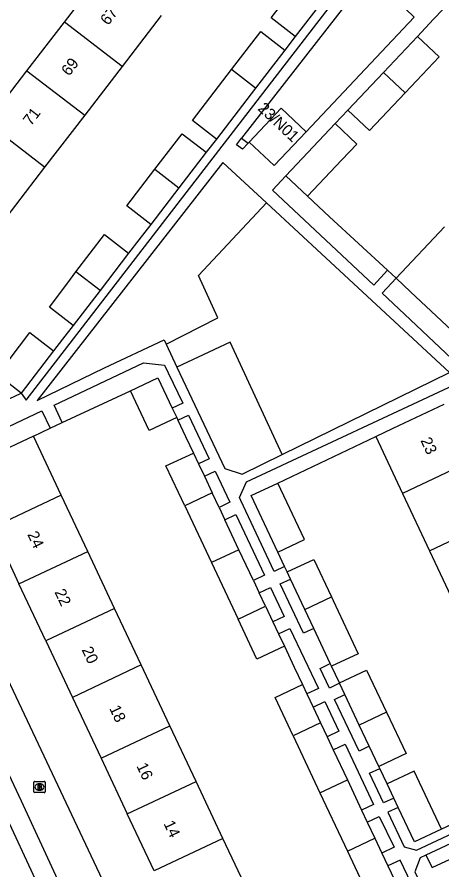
# Model space of a CAD drawing. Extents: x 159040 to 160094, y 381214 to 382518.
# Drawn here: x 159164.4 to 159201.9, y 381381.3 to 381456.6 of the extents above; entities that cross this region are included whole.
import ezdxf

# ---------------------------------------------------------------- set-up
doc = ezdxf.new("R2010")
doc.units = 0
for name, color, linetype in [('IMGEO_Brandkraan', 7, 'Continuous'), ('IMGEO_Groenvoorziening', 7, 'Continuous'), ('IMGEO_Pand', 7, 'Continuous'), ('IMGEO_Pand_nummerreeks', 7, 'Continuous'), ('IMGEO_Rijbaan_lokaal_open', 7, 'Continuous'), ('IMGEO_Voetpad_open', 7, 'Continuous')]:
    doc.layers.add(name, color=color, linetype=linetype)

msp = doc.modelspace()

# ---------------------------------------------------------------- linework, layer by layer
at = {"layer": 'IMGEO_Brandkraan'}
for p, q in [((159165.843, 381388.151), (159165.843, 381389.003)), ((159165.918, 381389.077), (159166.77, 381389.077)), ((159166.331, 381388.857), (159166.356, 381388.857)), ((159166.844, 381389.003), (159166.844, 381388.151)), ((159166.77, 381388.077), (159165.918, 381388.077)), ((159166.354, 381388.297), (159166.329, 381388.297))]:
    msp.add_line(p, q, dxfattribs=at)
for points in [[(159165.843, 381388.151), (159165.843, 381389.003)], [(159165.918, 381389.077), (159166.77, 381389.077)], [(159166.191, 381388.777), (159166.191, 381388.377), (159166.404, 381388.377)], [(159166.422, 381388.777), (159166.191, 381388.777)], [(159166.37, 381388.696), (159166.316, 381388.696), (159166.316, 381388.62)], [(159166.844, 381389.003), (159166.844, 381388.151)], [(159166.77, 381388.077), (159165.918, 381388.077)], [(159166.316, 381388.62), (159166.369, 381388.62)], [(159166.378, 381388.544), (159166.316, 381388.544), (159166.316, 381388.463)], [(159166.316, 381388.463), (159166.378, 381388.463)]]:
    msp.add_lwpolyline(points, dxfattribs=at)
for centre, radius, start, end in [((159165.92, 381389.001), 0.0765, 91.55205, 178.44795), ((159165.92, 381389.001), 0.0765, 91.55205, 178.44795), ((159166.371, 381388.658), 0.0379, 267.82845, 90.93552), ((159166.426, 381388.632), 0.145, 59.4692, 91.53667), ((159166.451, 381388.679), 0.0922, 285.51372, 58.15012), ((159166.768, 381389.001), 0.0765, 1.55205, 88.44795), ((159166.768, 381389.001), 0.0765, 1.55205, 88.44795), ((159165.92, 381388.153), 0.0765, 181.55205, 268.44795), ((159165.92, 381388.153), 0.0765, 181.55205, 268.44795), ((159166.379, 381388.503), 0.0404, 269.87594, 90.50774), ((159166.41, 381388.628), 0.251, 268.66757, 293.53466), ((159166.456, 381388.487), 0.105, 301.31148, 78.98903), ((159166.768, 381388.153), 0.0765, 271.55205, 358.44795), ((159166.768, 381388.153), 0.0765, 271.55205, 358.44795)]:
    msp.add_arc(centre, radius, start, end, dxfattribs=at)
for centre, major_axis, ratio, start_param, end_param in [((159166.33, 381388.577), (-0.387, 0.002), 0.722429, 4.712389, 7.853982), ((159166.355, 381388.577), (-0.39, 0.002), 0.717154, 1.570796, 4.712389)]:
    msp.add_ellipse(centre, major_axis=major_axis, ratio=ratio, start_param=start_param, end_param=end_param, dxfattribs=at)
at = {"layer": 'IMGEO_Groenvoorziening'}
for points in [[(159188.951, 381454.87), (159188.021, 381453.661)], [(159181.982, 381445.811), (159181.077, 381444.635)], [(159197.1, 381434.226), (159191.975, 381438.93), (159190.037, 381440.758)], [(159177.541, 381427.677), (159182.111, 381430.01), (159180.393, 381433.751), (159186.402, 381440.174)], [(159176.18, 381438.27), (159175.127, 381436.901), (159174.226, 381435.729)], [(159169.317, 381429.348), (159168.391, 381428.145), (159167.593, 381427.107)], [(159187.798, 381417.935), (159183.191, 381427.88), (159178.496, 381425.656)], [(159168.362, 381420.766), (159174.389, 381423.58)], [(159178.583, 381420.967), (159179.258, 381419.536), (159179.948, 381418.072)], [(159165.805, 381419.572), (159167.281, 381420.261)], [(159187.402, 381415.418), (159196.055, 381419.537)], [(159188.009, 381408.05), (159187.41, 381409.321)], [(159187.987, 381401.016), (159188.86, 381399.164), (159189.585, 381397.625)], [(159192.852, 381397.776), (159192.158, 381399.248)], [(159197.057, 381388.853), (159196.416, 381390.214)], [(159200.494, 381382.57), (159201.05, 381381.464), (159217.322, 381389.003)], [(159210.505, 381388.881), (159201.876, 381384.861)]]:
    msp.add_lwpolyline(points, dxfattribs=at)
at = {"layer": 'IMGEO_Pand'}
for points in [[(159188.951, 381454.87), (159186.825, 381456.505), (159190.35, 381461.088)], [(159168.552, 381456.144), (159172.008, 381460.637)], [(159192.476, 381459.453), (159188.951, 381454.87)], [(159177.108, 381456.713), (159173.652, 381452.22)], [(159165.242, 381451.841), (159168.552, 381456.144)], [(159173.652, 381452.22), (159168.552, 381456.144)], [(159183.312, 381451.939), (159185.895, 381455.297), (159188.021, 381453.661)], [(159196.738, 381451.698), (159199.738, 381454.878)], [(159198.653, 381449.893), (159201.652, 381453.073), (159199.738, 381454.878)], [(159188.021, 381453.661), (159185.438, 381450.304)], [(159173.652, 381452.22), (159170.342, 381447.917)], [(159181.982, 381445.811), (159179.856, 381447.447), (159183.312, 381451.939)], [(159185.438, 381450.304), (159183.312, 381451.939)], [(159161.698, 381447.234), (159165.242, 381451.841)], [(159165.242, 381451.841), (159170.342, 381447.917)], [(159193.586, 381448.355), (159196.738, 381451.698)], [(159196.738, 381451.698), (159198.653, 381449.893)], [(159185.438, 381450.304), (159181.982, 381445.811)], [(159198.653, 381449.893), (159195.501, 381446.549), (159193.586, 381448.355)], [(159184.883, 381445.545), (159187.701, 381448.534), (159189.902, 381446.458)], [(159170.342, 381447.917), (159166.798, 381443.31)], [(159166.798, 381443.31), (159161.698, 381447.234)], [(159188.123, 381442.563), (159192.467, 381447.169)], [(159190.037, 381440.758), (159193.078, 381443.981), (159194.382, 381445.363), (159192.467, 381447.169)], [(159176.546, 381443.144), (159178.951, 381446.271), (159181.077, 381444.635)], [(159189.902, 381446.458), (159187.083, 381443.469), (159184.883, 381445.545)], [(159181.077, 381444.635), (159178.671, 381441.508)], [(159166.798, 381443.31), (159163.366, 381438.849)], [(159176.18, 381438.27), (159174.055, 381439.906), (159176.546, 381443.144)], [(159176.546, 381443.144), (159178.671, 381441.508)], [(159188.123, 381442.563), (159190.037, 381440.758)], [(159178.671, 381441.508), (159176.18, 381438.27)], [(159202.137, 381438.049), (159197.867, 381433.522)], [(159169.569, 381434.075), (159172.101, 381437.365), (159174.226, 381435.729)], [(159174.226, 381435.729), (159171.695, 381432.439)], [(159169.317, 381429.348), (159167.226, 381430.956), (159167.879, 381431.805), (159169.077, 381433.435), (159169.569, 381434.075)], [(159171.695, 381432.439), (159169.569, 381434.075)], [(159202.771, 381428.897), (159199.134, 381432.328), (159197.867, 381433.522)], [(159171.695, 381432.439), (159169.317, 381429.348)], [(159164.713, 381423.363), (159162.622, 381424.971), (159165.502, 381428.715), (159167.593, 381427.107)], [(159167.593, 381427.107), (159164.713, 381423.363)], [(159174.389, 381423.58), (159176.813, 381424.723), (159178.082, 381422.031)], [(159178.471, 381421.205), (159176.047, 381420.063), (159174.389, 381423.58)], [(159178.082, 381422.031), (159178.471, 381421.205)], [(159196.055, 381419.537), (159197.587, 381420.259), (159202.109, 381422.391)], [(159165.805, 381419.572), (159164.247, 381418.838), (159159.724, 381416.706)], [(159168.264, 381414.355), (159165.805, 381419.572)], [(159196.055, 381419.537), (159198.423, 381414.513)], [(159179.176, 381413.425), (159177.523, 381416.93), (159179.948, 381418.072)], [(159179.948, 381418.072), (159180.398, 381417.118)], [(159204.477, 381417.367), (159198.423, 381414.513)], [(159180.398, 381417.118), (159180.914, 381416.022)], [(159180.914, 381416.022), (159181.6, 381414.567)], [(159187.41, 381409.321), (159185.057, 381414.313), (159187.402, 381415.418)], [(159187.41, 381409.321), (159189.755, 381410.427), (159187.402, 381415.418)], [(159168.264, 381414.355), (159162.183, 381411.489)], [(159170.606, 381409.386), (159168.264, 381414.355)], [(159181.6, 381414.567), (159179.176, 381413.425)], [(159182.21, 381413.274), (159181.6, 381414.567)], [(159198.423, 381414.513), (159200.81, 381409.45)], [(159179.176, 381413.425), (159181.546, 381408.395)], [(159182.21, 381413.274), (159182.727, 381412.176)], [(159183.971, 381409.537), (159182.727, 381412.176)], [(159200.81, 381409.45), (159206.864, 381412.303)], [(159162.183, 381411.489), (159164.525, 381406.52)], [(159164.525, 381406.52), (159170.606, 381409.386)], [(159172.977, 381404.356), (159170.606, 381409.386)], [(159183.971, 381409.537), (159181.546, 381408.395)], [(159185.258, 381406.805), (159183.971, 381409.537)], [(159200.81, 381409.45), (159203.172, 381404.439)], [(159181.546, 381408.395), (159183.903, 381403.396)], [(159188.231, 381407.58), (159190.575, 381408.686), (159192.141, 381405.364)], [(159188.531, 381406.942), (159188.231, 381407.58)], [(159185.258, 381406.805), (159185.77, 381405.72)], [(159189.796, 381404.259), (159188.531, 381406.942)], [(159166.896, 381401.49), (159164.525, 381406.52)], [(159186.327, 381404.538), (159185.77, 381405.72)], [(159189.796, 381404.259), (159192.141, 381405.364)], [(159192.141, 381405.364), (159192.294, 381405.039), (159194.5, 381400.352), (159192.158, 381399.248)], [(159183.903, 381403.396), (159186.327, 381404.538)], [(159186.327, 381404.538), (159186.977, 381403.158)], [(159172.977, 381404.356), (159166.896, 381401.49)], [(159175.333, 381399.357), (159172.977, 381404.356)], [(159190.585, 381402.585), (159189.796, 381404.259)], [(159187.987, 381401.016), (159185.563, 381399.874), (159183.903, 381403.396)], [(159186.977, 381403.158), (159187.475, 381402.102)], [(159192.047, 381399.483), (159190.585, 381402.585)], [(159166.896, 381401.49), (159169.252, 381396.491)], [(159187.475, 381402.102), (159187.987, 381401.016)], [(159175.333, 381399.357), (159169.252, 381396.491)], [(159177.866, 381393.983), (159175.333, 381399.357)], [(159192.158, 381399.248), (159192.047, 381399.483)], [(159192.852, 381397.776), (159195.255, 381398.909), (159197.01, 381395.185)], [(159192.871, 381397.736), (159192.852, 381397.776)], [(159193.339, 381396.744), (159192.871, 381397.736)], [(159188.751, 381393.11), (159187.161, 381396.483), (159189.585, 381397.625)], [(159189.585, 381397.625), (159189.972, 381396.804)], [(159169.252, 381396.491), (159171.785, 381391.117)], [(159189.972, 381396.804), (159190.524, 381395.633)], [(159194.607, 381394.053), (159193.339, 381396.744)], [(159190.524, 381395.633), (159191.175, 381394.252)], [(159197.01, 381395.185), (159194.607, 381394.053)], [(159197.01, 381395.185), (159198.735, 381391.527), (159196.331, 381390.394)], [(159171.785, 381391.117), (159177.866, 381393.983)], [(159180.181, 381389.071), (159177.866, 381393.983)], [(159191.175, 381394.252), (159188.751, 381393.11)], [(159191.175, 381394.252), (159191.763, 381393.005)], [(159195.492, 381392.174), (159194.607, 381394.053)], [(159188.751, 381393.11), (159191.127, 381388.068)], [(159191.763, 381393.005), (159192.307, 381391.851)], [(159192.307, 381391.851), (159193.551, 381389.21)], [(159196.331, 381390.394), (159195.492, 381392.174)], [(159171.785, 381391.117), (159174.1, 381386.205)], [(159201.876, 381384.861), (159199.461, 381389.986), (159197.057, 381388.853)], [(159174.1, 381386.205), (159180.181, 381389.071)], [(159182.558, 381384.029), (159180.181, 381389.071)], [(159191.127, 381388.068), (159193.551, 381389.21)], [(159193.551, 381389.21), (159194.812, 381386.536)], [(159197.647, 381387.601), (159197.057, 381388.853)], [(159191.127, 381388.068), (159193.552, 381382.924)], [(159198.037, 381386.775), (159197.647, 381387.601)], [(159194.812, 381386.536), (159195.31, 381385.478)], [(159201.876, 381384.861), (159199.473, 381383.728), (159198.037, 381386.775)], [(159176.477, 381381.163), (159174.1, 381386.205)], [(159195.31, 381385.478), (159195.976, 381384.066)], [(159182.558, 381384.029), (159176.477, 381381.163)], [(159184.982, 381378.885), (159182.558, 381384.029)], [(159193.552, 381382.924), (159195.976, 381384.066)], [(159195.976, 381384.066), (159196.602, 381382.737)], [(159193.552, 381382.924), (159196.403, 381376.874)], [(159196.602, 381382.737), (159197.136, 381381.605)], [(159197.136, 381381.605), (159198.827, 381378.016)]]:
    msp.add_lwpolyline(points, dxfattribs=at)
at = {"layer": 'IMGEO_Rijbaan_lokaal_open'}
msp.add_lwpolyline([(159152.42, 381409.329), (159163.115, 381386.6), (159166.148, 381380.052), (159173.158, 381365.109), (159175.314, 381360.345), (159181.799, 381346.618), (159183.007, 381344.058)], dxfattribs=at)
at = {"layer": 'IMGEO_Voetpad_open'}
for points in [[(159164.713, 381423.363), (159165.178, 381422.754), (159206.798, 381476.685), (159206.128, 381477.2)], [(159189.902, 381446.458), (159197.026, 381454.012), (159199.461, 381456.58), (159195.523, 381460.39), (159184.209, 381445.885)], [(159199.738, 381454.878), (159201.159, 381456.385), (159201.975, 381457.25)], [(159192.467, 381447.169), (159193.586, 381448.355)], [(159184.794, 381445.451), (159184.28, 381444.905), (159183.76, 381445.31), (159184.209, 381445.885)], [(159184.209, 381445.885), (159184.794, 381445.451)], [(159184.794, 381445.451), (159184.883, 381445.545)], [(159186.402, 381440.174), (159182.544, 381443.75), (159166.145, 381422.725), (159172.089, 381425.587), (159177.353, 381428.075), (159177.541, 381427.677)], [(159197.1, 381434.226), (159195.879, 381432.896), (159186.938, 381441.307), (159188.123, 381442.563)], [(159187.798, 381417.935), (159202.578, 381425.178), (159186.402, 381440.174)], [(159197.867, 381433.522), (159197.1, 381434.226)], [(159204.41, 381426.076), (159203.808, 381425.437), (159198.609, 381430.327), (159196.621, 381432.198), (159197.867, 381433.522)], [(159177.541, 381427.677), (159178.496, 381425.656)], [(159168.362, 381420.766), (159167.645, 381422.301), (159175.543, 381426.031), (159177.405, 381425.843), (159177.731, 381425.156), (159179.009, 381422.472), (159178.082, 381422.031)], [(159178.496, 381425.656), (159182.727, 381416.701), (159184.263, 381416.202), (159187.798, 381417.935)], [(159188.009, 381408.05), (159187.092, 381407.618), (159184.136, 381413.879), (159184.009, 381414.149), (159184.651, 381415.527), (159203.819, 381424.481)], [(159153.986, 381418.297), (159164.713, 381423.363)], [(159154.931, 381416.296), (159166.567, 381421.792), (159167.281, 381420.261)], [(159178.471, 381421.205), (159178.583, 381420.967)], [(159178.583, 381420.967), (159179.514, 381421.411), (159181.344, 381417.568), (159180.398, 381417.118)], [(159167.281, 381420.261), (159168.362, 381420.766)], [(159180.914, 381416.022), (159181.864, 381416.474), (159183.17, 381413.731), (159182.21, 381413.274)], [(159186.898, 381348.612), (159155.647, 381414.78)], [(159152.189, 381413.877), (159154.272, 381409.573), (159164.73, 381387.348), (159167.763, 381380.799), (159174.777, 381365.849), (159176.928, 381361.094), (159183.083, 381348.082), (159184.313, 381345.459)], [(159182.727, 381412.176), (159183.692, 381412.635), (159186.243, 381407.274), (159185.258, 381406.805)], [(159188.231, 381407.58), (159188.009, 381408.05)], [(159190.585, 381402.585), (159189.672, 381402.155), (159187.615, 381406.51), (159188.531, 381406.942)], [(159185.77, 381405.72), (159186.759, 381406.191), (159187.977, 381403.633), (159186.977, 381403.158)], [(159187.475, 381402.102), (159188.478, 381402.58), (159190.995, 381397.292), (159189.972, 381396.804)], [(159192.871, 381397.736), (159191.961, 381397.307), (159191.136, 381399.054), (159192.047, 381399.483)], [(159195.492, 381392.174), (159194.586, 381391.748), (159192.429, 381396.315), (159193.339, 381396.744)], [(159190.524, 381395.633), (159191.552, 381396.122), (159192.801, 381393.499), (159191.763, 381393.005)], [(159192.307, 381391.851), (159193.349, 381392.347), (159195.875, 381387.042), (159194.812, 381386.536)], [(159198.037, 381386.775), (159197.135, 381386.35), (159198.573, 381383.304), (159199.67, 381383.013), (159218.098, 381391.615)], [(159197.647, 381387.601), (159196.745, 381387.176), (159195.512, 381389.788), (159196.416, 381390.214)], [(159196.416, 381390.214), (159196.331, 381390.394)], [(159217.322, 381389.003), (159217.713, 381390.608), (159200.494, 381382.57)], [(159195.31, 381385.478), (159196.377, 381385.986), (159197.68, 381383.25), (159196.602, 381382.737)], [(159199.666, 381376.236), (159200.769, 381376.761), (159198.217, 381382.12), (159197.136, 381381.605)], [(159200.494, 381382.57), (159199.987, 381382.333), (159199.523, 381381.07), (159200.71, 381378.588)]]:
    msp.add_lwpolyline(points, dxfattribs=at)

# ---------------------------------------------------------------- texts
at = {"layer": 'IMGEO_Pand_nummerreeks'}
for s, rotation, p in [('67', 52.43048, (159172.417, 381455.789)), ('69', 52.43048, (159168.971, 381451.309)), ('23/N01', 316.63658, (159185.569, 381448.426)), ('71', 52.43048, (159165.594, 381446.919)), ('23', 295.23657, (159199.994, 381419.185)), ('24', 295.23609, (159165.251, 381410.89)), ('22', 295.23609, (159167.65, 381405.801)), ('20', 295.23609, (159170.053, 381400.704)), ('18', 295.23609, (159172.492, 381395.529)), ('16', 295.23609, (159174.89, 381390.441)), ('14', 295.23609, (159177.29, 381385.349))]:
    msp.add_text(s, height=1, rotation=rotation, dxfattribs=at).set_placement(p)

doc.saveas('drawing.dxf')
